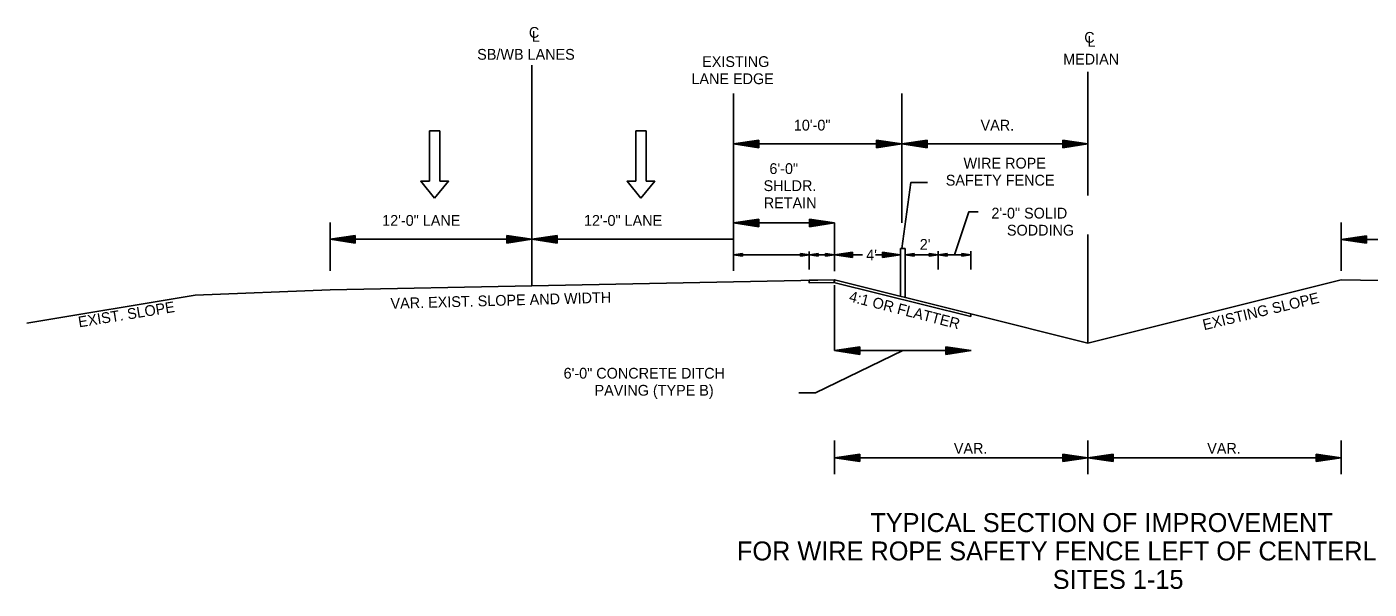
# Model space of a CAD drawing. Extents: x 1641422 to 1649187, y 577497 to 580642.
# Drawn here: x 1642752 to 1644249, y 577497 to 578123 of the extents above; entities that cross this region are included whole.
import ezdxf

# ---------------------------------------------------------------- set-up
doc = ezdxf.new("R2010")
doc.units = 0
doc.layers.add('Default', color=7, linetype='Continuous')
doc.layers.add('R_Draft', color=7, linetype='Continuous')

msp = doc.modelspace()

# ---------------------------------------------------------------- linework, layer by layer
at = {"layer": 'Default'}
for p, q in [((1643673, 577871.9), (1643653, 577868.9)), ((1643684.2, 577868.9), (1643653, 577868.9)), ((1643673, 577865.9), (1643653, 577868.9)), ((1643673, 577871.4), (1643656.4, 577868.9)), ((1643673, 577866.4), (1643656.4, 577868.9)), ((1643673, 577870.9), (1643659.8, 577868.9)), ((1643673, 577866.9), (1643659.8, 577868.9)), ((1643673, 577870.4), (1643663.2, 577868.9)), ((1643673, 577867.4), (1643663.2, 577868.9)), ((1643673, 577869.9), (1643666.5, 577868.9)), ((1643673, 577867.9), (1643666.5, 577868.9)), ((1643673, 577869.4), (1643669.9, 577868.9)), ((1643673, 577868.4), (1643669.9, 577868.9)), ((1643673, 577865.9), (1643673, 577871.9)), ((1643698.8, 577868.9), (1643726.5, 577868.9)), ((1643706.5, 577871.9), (1643726.5, 577868.9)), ((1643706.5, 577871.9), (1643706.5, 577865.9)), ((1643706.5, 577871.4), (1643723.2, 577868.9)), ((1643706.5, 577870.9), (1643719.7, 577868.9)), ((1643706.5, 577870.4), (1643716.4, 577868.9)), ((1643706.5, 577869.9), (1643713, 577868.9)), ((1643706.5, 577869.4), (1643709.7, 577868.9)), ((1643706.5, 577865.9), (1643726.5, 577868.9)), ((1643706.5, 577867.9), (1643713, 577868.9)), ((1643706.5, 577866.9), (1643719.7, 577868.9)), ((1643706.5, 577866.4), (1643723.2, 577868.9)), ((1643706.5, 577867.4), (1643716.4, 577868.9)), ((1643706.5, 577868.4), (1643709.7, 577868.9)), ((1643726.7, 577876.1), (1643731.7, 577876.1)), ((1643726.7, 577876.1), (1643726.7, 577822.9)), ((1643731.7, 577876.1), (1643731.7, 577821.7)), ((1643741.7, 577870.4), (1643731.7, 577868.9)), ((1643768.4, 577868.9), (1643731.7, 577868.9)), ((1643741.7, 577867.4), (1643731.7, 577868.9)), ((1643741.7, 577870.1), (1643733.4, 577868.9)), ((1643741.7, 577867.6), (1643733.4, 577868.9)), ((1643741.7, 577869.9), (1643735.1, 577868.9)), ((1643741.7, 577867.9), (1643735.1, 577868.9)), ((1643741.7, 577869.6), (1643736.7, 577868.9)), ((1643741.7, 577868.1), (1643736.7, 577868.9)), ((1643741.7, 577869.4), (1643738.4, 577868.9)), ((1643741.7, 577868.4), (1643738.4, 577868.9)), ((1643741.7, 577869.1), (1643740.1, 577868.9)), ((1643741.7, 577868.7), (1643740.1, 577868.9)), ((1643741.7, 577867.4), (1643741.7, 577870.4)), ((1643758.4, 577870.4), (1643768.4, 577868.9)), ((1643758.4, 577870.4), (1643758.4, 577867.4)), ((1643758.4, 577870.1), (1643766.7, 577868.9)), ((1643758.4, 577869.9), (1643765, 577868.9)), ((1643758.4, 577869.6), (1643763.4, 577868.9)), ((1643758.4, 577869.4), (1643761.7, 577868.9)), ((1643758.4, 577869.1), (1643760, 577868.9)), ((1643758.4, 577867.4), (1643768.4, 577868.9)), ((1643758.4, 577868.4), (1643761.7, 577868.9)), ((1643758.4, 577867.9), (1643765, 577868.9)), ((1643758.4, 577867.6), (1643766.7, 577868.9)), ((1643758.4, 577868.1), (1643763.4, 577868.9)), ((1643758.4, 577868.7), (1643760, 577868.9)), ((1643778.4, 577870.4), (1643768.4, 577868.9)), ((1643778.4, 577867.4), (1643768.4, 577868.9)), ((1643805.1, 577868.9), (1643768.4, 577868.9)), ((1643778.4, 577870.1), (1643770.1, 577868.9)), ((1643778.4, 577867.6), (1643770.1, 577868.9)), ((1643778.4, 577869.9), (1643771.8, 577868.9)), ((1643778.4, 577867.9), (1643771.8, 577868.9)), ((1643778.4, 577869.6), (1643773.5, 577868.9)), ((1643778.4, 577868.1), (1643773.5, 577868.9)), ((1643778.4, 577869.4), (1643775.2, 577868.9)), ((1643778.4, 577868.4), (1643775.2, 577868.9)), ((1643778.4, 577869.1), (1643776.8, 577868.9)), ((1643778.4, 577868.7), (1643776.8, 577868.9)), ((1643777.9, 577868.9), (1643802.3, 577868.9)), ((1643778.4, 577867.4), (1643778.4, 577870.4)), ((1643795.1, 577870.4), (1643805.1, 577868.9)), ((1643795.1, 577870.4), (1643795.1, 577867.4)), ((1643795.1, 577870.1), (1643803.5, 577868.9)), ((1643795.1, 577869.9), (1643801.7, 577868.9)), ((1643795.1, 577869.6), (1643800.1, 577868.9)), ((1643795.1, 577869.4), (1643798.4, 577868.9)), ((1643795.1, 577869.1), (1643796.7, 577868.9)), ((1643795.1, 577867.4), (1643805.1, 577868.9)), ((1643795.1, 577868.4), (1643798.4, 577868.9)), ((1643795.1, 577867.9), (1643801.7, 577868.9)), ((1643795.1, 577867.6), (1643803.5, 577868.9)), ((1643795.1, 577868.1), (1643800.1, 577868.9)), ((1643795.1, 577868.7), (1643796.7, 577868.9)), ((1643624.6, 577837.8), (1643624.6, 577840.7)), ((1643653.1, 577838.3), (1643624.6, 577837.8)), ((1643652.3, 577838.3), (1643653, 577841.3)), ((1643805.1, 577800.1), (1643652.3, 577838.3)), ((1643805.1, 577803.3), (1643653, 577841.3)), ((1643935.5, 577770.7), (1644218, 577841.3)), ((1643935.5, 577770.7), (1643805.1, 577803.3)), ((1643805.1, 577800.1), (1643805.1, 577803.3))]:
    msp.add_line(p, q, dxfattribs=at)
msp.add_lwpolyline([(1643624.6, 577840.7), (1643653, 577841.3), (1643653.1, 577838.3), (1643624.6, 577837.8)], close=True, dxfattribs=at)
at = {"layer": 'R_Draft'}
for p, q in [((1643315.6, 577904.9), (1643315.6, 578080.3)), ((1643935.5, 577935), (1643935.5, 578072.9)), ((1643540.5, 577851), (1643540.5, 578048.8)), ((1643728, 577904.6), (1643728, 578048.8)), ((1643213, 578007), (1643201.3, 578007)), ((1643201.3, 577950.9), (1643201.3, 578007)), ((1643213, 577950.9), (1643213, 578007)), ((1643443, 578007), (1643431.3, 578007)), ((1643431.3, 577950.9), (1643431.3, 578007)), ((1643443, 577950.9), (1643443, 578007)), ((1643568.7, 577996.7), (1643540.5, 577992.5)), ((1643728, 577992.5), (1643540.5, 577992.5)), ((1643568.7, 577988.2), (1643540.5, 577992.5)), ((1643568.7, 577996), (1643545.2, 577992.5)), ((1643568.7, 577988.9), (1643545.2, 577992.5)), ((1643568.7, 577995.3), (1643550.1, 577992.5)), ((1643568.7, 577989.7), (1643550.1, 577992.5)), ((1643568.7, 577994.6), (1643554.8, 577992.5)), ((1643568.7, 577990.4), (1643554.8, 577992.5)), ((1643568.7, 577993.8), (1643559.5, 577992.5)), ((1643568.7, 577991.1), (1643559.5, 577992.5)), ((1643568.7, 577993.1), (1643564.2, 577992.5)), ((1643568.7, 577991.8), (1643564.2, 577992.5)), ((1643568.7, 577988.2), (1643568.7, 577996.7)), ((1643699.9, 577996.7), (1643728, 577992.5)), ((1643699.9, 577996.7), (1643699.9, 577988.2)), ((1643699.9, 577996), (1643723.4, 577992.5)), ((1643699.9, 577995.3), (1643718.5, 577992.5)), ((1643699.9, 577994.6), (1643713.8, 577992.5)), ((1643699.9, 577993.8), (1643709.1, 577992.5)), ((1643699.9, 577993.1), (1643704.4, 577992.5)), ((1643699.9, 577988.2), (1643728, 577992.5)), ((1643699.9, 577991.1), (1643709.1, 577992.5)), ((1643699.9, 577989.7), (1643718.5, 577992.5)), ((1643699.9, 577988.9), (1643723.4, 577992.5)), ((1643699.9, 577990.4), (1643713.8, 577992.5)), ((1643699.9, 577991.8), (1643704.4, 577992.5)), ((1643756.2, 577996.7), (1643728, 577992.5)), ((1643756.2, 577988.2), (1643728, 577992.5)), ((1643935.5, 577992.5), (1643728, 577992.5)), ((1643756.2, 577996), (1643732.7, 577992.5)), ((1643756.2, 577988.9), (1643732.7, 577992.5)), ((1643756.2, 577995.3), (1643737.6, 577992.5)), ((1643756.2, 577989.7), (1643737.6, 577992.5)), ((1643756.2, 577994.6), (1643742.3, 577992.5)), ((1643756.2, 577990.4), (1643742.3, 577992.5)), ((1643756.2, 577993.8), (1643747, 577992.5)), ((1643756.2, 577991.1), (1643747, 577992.5)), ((1643756.2, 577993.1), (1643751.7, 577992.5)), ((1643756.2, 577991.8), (1643751.7, 577992.5)), ((1643756.2, 577988.2), (1643756.2, 577996.7)), ((1643907.4, 577996.7), (1643935.5, 577992.5)), ((1643907.4, 577996.7), (1643907.4, 577988.2)), ((1643907.4, 577996), (1643930.8, 577992.5)), ((1643907.4, 577995.3), (1643926, 577992.5)), ((1643907.4, 577994.6), (1643921.3, 577992.5)), ((1643907.4, 577993.8), (1643916.5, 577992.5)), ((1643907.4, 577993.1), (1643911.8, 577992.5)), ((1643907.4, 577988.2), (1643935.5, 577992.5)), ((1643907.4, 577991.1), (1643916.5, 577992.5)), ((1643907.4, 577989.7), (1643926, 577992.5)), ((1643907.4, 577988.9), (1643930.8, 577992.5)), ((1643907.4, 577990.4), (1643921.3, 577992.5)), ((1643907.4, 577991.8), (1643911.8, 577992.5)), ((1643090.6, 577851.3), (1643090.6, 577904.9)), ((1643090.6, 577851), (1643090.6, 577904.9)), ((1643315.6, 577851), (1643315.6, 577904.9)), ((1643568.7, 577908.8), (1643540.5, 577904.6)), ((1643653, 577904.6), (1643540.5, 577904.6)), ((1643568.7, 577900.3), (1643540.5, 577904.6)), ((1643568.7, 577908.1), (1643545.2, 577904.6)), ((1643568.7, 577901), (1643545.2, 577904.6)), ((1643568.7, 577907.4), (1643550.1, 577904.6)), ((1643568.7, 577901.8), (1643550.1, 577904.6)), ((1643568.7, 577906.6), (1643554.8, 577904.6)), ((1643568.7, 577902.5), (1643554.8, 577904.6)), ((1643568.7, 577905.9), (1643559.5, 577904.6)), ((1643568.7, 577903.2), (1643559.5, 577904.6)), ((1643568.7, 577905.2), (1643564.2, 577904.6)), ((1643568.7, 577903.9), (1643564.2, 577904.6)), ((1643568.7, 577900.3), (1643568.7, 577908.8)), ((1643624.9, 577908.8), (1643653, 577904.6)), ((1643624.9, 577908.8), (1643624.9, 577900.3)), ((1643624.9, 577908.1), (1643648.4, 577904.6)), ((1643624.9, 577907.4), (1643643.5, 577904.6)), ((1643624.9, 577906.6), (1643638.8, 577904.6)), ((1643624.9, 577905.9), (1643634.1, 577904.6)), ((1643624.9, 577905.2), (1643629.4, 577904.6)), ((1643624.9, 577900.3), (1643653, 577904.6)), ((1643624.9, 577903.2), (1643634.1, 577904.6)), ((1643624.9, 577901.8), (1643643.5, 577904.6)), ((1643624.9, 577901), (1643648.4, 577904.6)), ((1643624.9, 577902.5), (1643638.8, 577904.6)), ((1643624.9, 577903.9), (1643629.4, 577904.6)), ((1643653, 577850.7), (1643653, 577904.6)), ((1644218, 577851), (1644218, 577904.9)), ((1643118.7, 577890.5), (1643090.6, 577886.3)), ((1643315.6, 577886.3), (1643090.6, 577886.3)), ((1643118.7, 577882.1), (1643090.6, 577886.3)), ((1643118.7, 577889.8), (1643095.3, 577886.3)), ((1643118.7, 577882.8), (1643095.3, 577886.3)), ((1643118.7, 577889.1), (1643100.1, 577886.3)), ((1643118.7, 577883.5), (1643100.1, 577886.3)), ((1643118.7, 577888.4), (1643104.8, 577886.3)), ((1643118.7, 577884.2), (1643104.8, 577886.3)), ((1643118.7, 577887.7), (1643109.6, 577886.3)), ((1643118.7, 577885), (1643109.6, 577886.3)), ((1643118.7, 577887), (1643114.3, 577886.3)), ((1643118.7, 577885.7), (1643114.3, 577886.3)), ((1643118.7, 577882.1), (1643118.7, 577890.5)), ((1643287.5, 577890.5), (1643315.6, 577886.3)), ((1643287.5, 577890.5), (1643287.5, 577882.1)), ((1643287.5, 577889.8), (1643310.9, 577886.3)), ((1643287.5, 577889.1), (1643306, 577886.3)), ((1643287.5, 577888.4), (1643301.4, 577886.3)), ((1643287.5, 577887.7), (1643296.6, 577886.3)), ((1643287.5, 577887), (1643291.9, 577886.3)), ((1643287.5, 577882.1), (1643315.6, 577886.3)), ((1643287.5, 577884.9), (1643296.6, 577886.3)), ((1643287.5, 577883.5), (1643306, 577886.3)), ((1643287.5, 577882.8), (1643310.9, 577886.3)), ((1643287.5, 577884.2), (1643301.4, 577886.3)), ((1643287.5, 577885.7), (1643291.9, 577886.3)), ((1643540.5, 577886.3), (1643315.5, 577886.3)), ((1643343.7, 577890.5), (1643315.6, 577886.3)), ((1643343.7, 577882.1), (1643315.6, 577886.3)), ((1643343.7, 577889.8), (1643320.3, 577886.3)), ((1643343.7, 577882.8), (1643320.3, 577886.3)), ((1643343.7, 577889.1), (1643325.1, 577886.3)), ((1643343.7, 577883.5), (1643325.1, 577886.3)), ((1643343.7, 577888.4), (1643329.8, 577886.3)), ((1643343.7, 577884.2), (1643329.8, 577886.3)), ((1643343.7, 577887.7), (1643334.6, 577886.3)), ((1643343.7, 577885), (1643334.6, 577886.3)), ((1643343.7, 577887), (1643339.3, 577886.3)), ((1643343.7, 577885.7), (1643339.3, 577886.3)), ((1643343.7, 577882.1), (1643343.7, 577890.5)), ((1643935.5, 577770.7), (1643935.5, 577891.7)), ((1644246.1, 577890.2), (1644218, 577886)), ((1644330.5, 577886), (1644218, 577886)), ((1644246.1, 577881.8), (1644218, 577886)), ((1644246.1, 577889.5), (1644222.7, 577886)), ((1644246.1, 577882.5), (1644222.7, 577886)), ((1644246.1, 577888.8), (1644227.5, 577886)), ((1644246.1, 577883.2), (1644227.5, 577886)), ((1644246.1, 577888.1), (1644232.2, 577886)), ((1644246.1, 577883.9), (1644232.2, 577886)), ((1644246.1, 577887.4), (1644236.9, 577886)), ((1644246.1, 577884.6), (1644236.9, 577886)), ((1644246.1, 577886.7), (1644241.6, 577886)), ((1644246.1, 577885.3), (1644241.6, 577886)), ((1644246.1, 577881.8), (1644246.1, 577890.2)), ((1643550.5, 577870.4), (1643540.5, 577868.9)), ((1643624.9, 577868.9), (1643540.5, 577868.9)), ((1643550.5, 577867.4), (1643540.5, 577868.9)), ((1643550.5, 577870.1), (1643542.2, 577868.9)), ((1643550.5, 577867.6), (1643542.2, 577868.9)), ((1643550.5, 577869.9), (1643543.9, 577868.9)), ((1643550.5, 577867.9), (1643543.9, 577868.9)), ((1643550.5, 577869.6), (1643545.6, 577868.9)), ((1643550.5, 577868.1), (1643545.6, 577868.9)), ((1643550.5, 577869.4), (1643547.3, 577868.9)), ((1643550.5, 577868.4), (1643547.3, 577868.9)), ((1643550.5, 577869.1), (1643549, 577868.9)), ((1643550.5, 577868.7), (1643549, 577868.9)), ((1643550.5, 577870.4), (1643550.5, 577867.4)), ((1643614.9, 577870.4), (1643624.9, 577868.9)), ((1643614.9, 577867.4), (1643614.9, 577870.4)), ((1643614.9, 577870.1), (1643623.3, 577868.9)), ((1643614.9, 577869.9), (1643621.5, 577868.9)), ((1643614.9, 577869.6), (1643619.9, 577868.9)), ((1643614.9, 577869.4), (1643618.2, 577868.9)), ((1643614.9, 577869.1), (1643616.5, 577868.9)), ((1643614.9, 577867.4), (1643624.9, 577868.9)), ((1643614.9, 577868.4), (1643618.2, 577868.9)), ((1643614.9, 577867.9), (1643621.5, 577868.9)), ((1643614.9, 577867.6), (1643623.3, 577868.9)), ((1643614.9, 577868.1), (1643619.9, 577868.9)), ((1643614.9, 577868.7), (1643616.5, 577868.9)), ((1643624.6, 577872.5), (1643624.6, 577852.6)), ((1643634.9, 577870.4), (1643624.9, 577868.9)), ((1643653, 577868.9), (1643624.9, 577868.9)), ((1643634.9, 577867.4), (1643624.9, 577868.9)), ((1643634.9, 577870.1), (1643626.6, 577868.9)), ((1643634.9, 577867.6), (1643626.6, 577868.9)), ((1643634.9, 577869.9), (1643628.3, 577868.9)), ((1643634.9, 577867.9), (1643628.3, 577868.9)), ((1643634.9, 577869.6), (1643630, 577868.9)), ((1643634.9, 577868.1), (1643630, 577868.9)), ((1643634.9, 577869.4), (1643631.7, 577868.9)), ((1643634.9, 577868.4), (1643631.7, 577868.9)), ((1643634.9, 577869.1), (1643633.3, 577868.9)), ((1643634.9, 577868.7), (1643633.3, 577868.9)), ((1643634.9, 577870.4), (1643634.9, 577867.4)), ((1643643, 577870.4), (1643653, 577868.9)), ((1643643, 577867.4), (1643643, 577870.4)), ((1643643, 577870.1), (1643651.4, 577868.9)), ((1643643, 577869.9), (1643649.7, 577868.9)), ((1643643, 577869.6), (1643648, 577868.9)), ((1643643, 577869.4), (1643646.3, 577868.9)), ((1643643, 577869.1), (1643644.6, 577868.9)), ((1643643, 577867.4), (1643653, 577868.9)), ((1643643, 577868.4), (1643646.3, 577868.9)), ((1643643, 577867.9), (1643649.7, 577868.9)), ((1643643, 577867.6), (1643651.4, 577868.9)), ((1643643, 577868.1), (1643648, 577868.9)), ((1643643, 577868.7), (1643644.6, 577868.9)), ((1643768.4, 577873.1), (1643768.4, 577852.6)), ((1643805.1, 577873.1), (1643805.1, 577852.6)), ((1643315.6, 577834.6), (1643315.6, 577852.8)), ((1643653, 577841.3), (1643315.6, 577834.6)), ((1644218, 577841.3), (1644555.5, 577834.6)), ((1642940.1, 577824), (1642752.5, 577792.8)), ((1642940.1, 577824), (1643090.6, 577830.1)), ((1643315.6, 577834.6), (1643090.6, 577830.1)), ((1643653, 577762.3), (1643653, 577835.2)), ((1643681.2, 577766.5), (1643653, 577762.3)), ((1643681.2, 577758), (1643653, 577762.3)), ((1643805.2, 577762.3), (1643653, 577762.3)), ((1643681.2, 577765.8), (1643657.7, 577762.3)), ((1643681.2, 577758.7), (1643657.7, 577762.3)), ((1643681.2, 577765.1), (1643662.6, 577762.3)), ((1643681.2, 577759.5), (1643662.6, 577762.3)), ((1643681.2, 577764.4), (1643667.3, 577762.3)), ((1643681.2, 577760.2), (1643667.3, 577762.3)), ((1643681.2, 577763.6), (1643672, 577762.3)), ((1643681.2, 577760.9), (1643672, 577762.3)), ((1643681.2, 577762.9), (1643676.7, 577762.3)), ((1643681.2, 577761.6), (1643676.7, 577762.3)), ((1643681.2, 577758), (1643681.2, 577766.5)), ((1643777.1, 577766.5), (1643805.2, 577762.3)), ((1643777.1, 577766.5), (1643777.1, 577758)), ((1643777.1, 577765.8), (1643800.5, 577762.3)), ((1643777.1, 577765.1), (1643795.7, 577762.3)), ((1643777.1, 577764.4), (1643791, 577762.3)), ((1643777.1, 577763.6), (1643786.2, 577762.3)), ((1643777.1, 577762.9), (1643781.5, 577762.3)), ((1643777.1, 577758), (1643805.2, 577762.3)), ((1643777.1, 577760.9), (1643786.2, 577762.3)), ((1643777.1, 577759.5), (1643795.7, 577762.3)), ((1643777.1, 577758.7), (1643800.5, 577762.3)), ((1643777.1, 577760.2), (1643791, 577762.3)), ((1643777.1, 577761.6), (1643781.5, 577762.3)), ((1643653, 577662.1), (1643653, 577624.6)), ((1643935.5, 577662.1), (1643935.5, 577624.6)), ((1644218, 577662.1), (1644218, 577624.6)), ((1643681.2, 577647.1), (1643653, 577642.9)), ((1643653, 577642.9), (1643935.5, 577642.9)), ((1643681.2, 577638.7), (1643653, 577642.9)), ((1643681.2, 577646.4), (1643657.7, 577642.9)), ((1643681.2, 577639.4), (1643657.7, 577642.9)), ((1643681.2, 577645.7), (1643662.6, 577642.9)), ((1643681.2, 577640.1), (1643662.6, 577642.9)), ((1643681.2, 577645), (1643667.3, 577642.9)), ((1643681.2, 577640.8), (1643667.3, 577642.9)), ((1643681.2, 577644.3), (1643672, 577642.9)), ((1643681.2, 577641.5), (1643672, 577642.9)), ((1643681.2, 577643.6), (1643676.7, 577642.9)), ((1643681.2, 577642.2), (1643676.7, 577642.9)), ((1643681.2, 577638.7), (1643681.2, 577647.1)), ((1643907.4, 577647.1), (1643935.5, 577642.9)), ((1643907.4, 577647.1), (1643907.4, 577638.7)), ((1643907.4, 577646.4), (1643930.8, 577642.9)), ((1643907.4, 577645.7), (1643926, 577642.9)), ((1643907.4, 577645), (1643921.3, 577642.9)), ((1643907.4, 577644.3), (1643916.5, 577642.9)), ((1643907.4, 577643.6), (1643911.8, 577642.9)), ((1643907.4, 577638.7), (1643935.5, 577642.9)), ((1643907.4, 577641.5), (1643916.5, 577642.9)), ((1643907.4, 577640.1), (1643926, 577642.9)), ((1643907.4, 577639.4), (1643930.8, 577642.9)), ((1643907.4, 577640.8), (1643921.3, 577642.9)), ((1643907.4, 577642.2), (1643911.8, 577642.9)), ((1643963.6, 577647.1), (1643935.5, 577642.9)), ((1643935.5, 577642.9), (1644218, 577642.9)), ((1643963.6, 577638.7), (1643935.5, 577642.9)), ((1643963.6, 577646.4), (1643940.2, 577642.9)), ((1643963.6, 577639.4), (1643940.2, 577642.9)), ((1643963.6, 577645.7), (1643945, 577642.9)), ((1643963.6, 577640.1), (1643945, 577642.9)), ((1643963.6, 577645), (1643949.7, 577642.9)), ((1643963.6, 577640.8), (1643949.7, 577642.9)), ((1643963.6, 577644.3), (1643954.5, 577642.9)), ((1643963.6, 577641.5), (1643954.5, 577642.9)), ((1643963.6, 577643.6), (1643959.2, 577642.9)), ((1643963.6, 577642.2), (1643959.2, 577642.9)), ((1643963.6, 577638.7), (1643963.6, 577647.1)), ((1644189.8, 577647.1), (1644218, 577642.9)), ((1644189.8, 577647.1), (1644189.8, 577638.7)), ((1644189.8, 577646.4), (1644213.3, 577642.9)), ((1644189.8, 577645.7), (1644208.4, 577642.9)), ((1644189.8, 577645), (1644203.7, 577642.9)), ((1644189.8, 577644.3), (1644199, 577642.9)), ((1644189.8, 577643.6), (1644194.3, 577642.9)), ((1644189.8, 577638.7), (1644218, 577642.9)), ((1644189.8, 577641.5), (1644199, 577642.9)), ((1644189.8, 577640.1), (1644208.4, 577642.9)), ((1644189.8, 577639.4), (1644213.3, 577642.9)), ((1644189.8, 577640.8), (1644203.7, 577642.9)), ((1644189.8, 577642.2), (1644194.3, 577642.9)), ((1644189.8, 577642.9), (1644218, 577642.9))]:
    msp.add_line(p, q, dxfattribs=at)
for points in [[(1643201.3, 577950.9), (1643191.7, 577950.9), (1643207.1, 577932.1)], [(1643213, 577950.9), (1643222.6, 577950.9), (1643207.1, 577932.1)], [(1643431.3, 577950.9), (1643421.7, 577950.9), (1643437.1, 577932.1)], [(1643443, 577950.9), (1643452.6, 577950.9), (1643437.1, 577932.1)], [(1643756.7, 577949.4), (1643737.9, 577949.4), (1643728, 577876.1)], [(1643813.2, 577917), (1643802.9, 577917), (1643786.8, 577868.9)], [(1643613.1, 577715.2), (1643631.9, 577715.2), (1643729.1, 577762.3)]]:
    msp.add_lwpolyline(points, dxfattribs=at)

# ---------------------------------------------------------------- texts
at = {"layer": 'Default'}
for s, p in [("2'", (1643748, 577874.6)), ("4'", (1643688.3, 577862.9))]:
    msp.add_text(s, height=12, dxfattribs=at).set_placement(p)
at = {"layer": 'R_Draft'}
for s, height, p in [('C', 12, (1643312.2, 578110.7)), ('L', 12, (1643315.6, 578106.3)), ('C', 12, (1643931.4, 578105.2)), ('L', 12, (1643934.9, 578100.8)), ('SB/WB LANES', 12, (1643254.6, 578086.3)), ('MEDIAN', 12, (1643907.9, 578080.9)), ('EXISTING', 12, (1643505.4, 578078.2)), ('LANE EDGE', 12, (1643493.4, 578059.1)), ('10\'-0"', 12, (1643607.6, 578007.4)), ('VAR.', 12, (1643815.8, 578007.4)), ('WIRE ROPE', 12, (1643796.8, 577965.1)), ('6\'-0"', 12, (1643580.4, 577959)), ('SAFETY FENCE', 12, (1643777, 577946.1)), ('SHLDR.', 12, (1643573.9, 577940)), ('RETAIN', 12, (1643574.1, 577920.9)), ('12\'-0" LANE', 12, (1643148.6, 577901.3)), ('12\'-0" LANE', 12, (1643373.6, 577901.3)), ('2\'-0" SOLID', 12, (1643827.9, 577909.4)), ('SODDING', 12, (1643845.2, 577890.4)), ('    6\'-0" CONCRETE DITCH', 12, (1643333.1, 577731.1)), ('PAVING (TYPE B)', 12, (1643385.4, 577712.1)), ('VAR.', 12, (1643786, 577647.4)), ('VAR.', 12, (1644068.5, 577647.4)), ('TYPICAL SECTION OF IMPROVEMENT', 21.094, (1643692.9, 577560.2)), ('FOR WIRE ROPE SAFETY FENCE LEFT OF CENTERLINE', 21.094, (1643544.2, 577528.6)), ('SITES 1-15', 21.09, (1643896.3, 577496.9))]:
    msp.add_text(s, height=height, dxfattribs=at).set_placement(p)
for s, rotation, p in [('VAR. EXIST. SLOPE AND WIDTH', 1.6096, (1643158.1, 577808.8)), ('4:1 OR FLATTER', 345.6653, (1643668.3, 577817.3)), ('EXISTING SLOPE', 13.4085, (1644065, 577784.9)), ('EXIST. SLOPE', 9.1534, (1642810.7, 577788.1))]:
    msp.add_text(s, height=12, rotation=rotation, dxfattribs=at).set_placement(p)

doc.saveas('drawing.dxf')
